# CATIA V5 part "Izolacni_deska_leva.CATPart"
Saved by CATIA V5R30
Part number: Izolacni_deska_leva
Definition: E 1400_396 446_8_90_1
Nomenclature: E 1400_396 446_8_90_1
Source: Unknown
Description: PART--DESC
Bounding box of the stored display mesh (mm): x -223 to 223, y -198 to 198, z -268 to -260
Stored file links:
  E:\Bakalarka\Model\Forma_v7\Izolacni_deska_leva.CATPart
  E:\Bakalarka\Model\Forma_v7\Vyhazovaci_cast.CATProduct
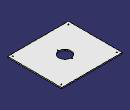
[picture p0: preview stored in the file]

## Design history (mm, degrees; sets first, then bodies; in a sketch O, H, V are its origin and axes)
Body1 "MANIFOLD_SOLID_BREP #3770" (main body)
  Solid1: solid without history
  Body2 "Result of DrillHole"
    Solid2: linked copy from another document
  Assemble1 "DrillHoleLocatingRing_E1362_3.1": tool Body2
  Body3 "Result of DrillHole"
    Solid3: linked copy from another document
  Assemble2 "DrillHoleCapScrew_E1200_1.1": tool Body3
  Body4 "Result of DrillHole"
    Solid4: linked copy from another document
  Assemble3 "DrillHoleCapScrew_E1200_1.2": tool Body4
  Body5 "Result of DrillHole"
    Solid5: linked copy from another document
  Assemble4 "DrillHoleCountersunkScrew_E1220_6.1": tool Body5
  Body6 "Result of DrillHole"
    Solid6: linked copy from another document
  Assemble5 "DrillHoleCountersunkScrew_E1220_6.2": tool Body6
  Body7 "Result of DrillHole"
    Solid7: linked copy from another document
  Assemble6 "DrillHoleCountersunkScrew_E1220_6.3": tool Body7
  Body8 "Result of DrillHole"
    Solid8: linked copy from another document
  Assemble7 "DrillHoleCountersunkScrew_E1220_6.4": tool Body8
  Body9 "Result of DrillHole"
    Solid9: linked copy from another document
  Assemble8 "DrillHoleLocatingRing_E1367_2.1": tool Body9
  Sketch1 on face of Solid1, origin (0, 0, -268), H (1, 0, 0), V (0, -1, 0)
    point P1 (0, 0)
    point P2 (170, 0)
    point P3 (-170, 0)
    distance V P2 = 170
    distance P3 V = 170
    coincidence: P1 O, P2 H, P3 H
  DatumPoint1
  DatumPoint2
  Sketch2 on face of Solid1, origin (0, 0, -268), H (1, 0, 0), V (0, -1, 0)
    point P1 (203.188, -177.0927)
    point P2 (203.188, 179.4827)
    projected point E1 (-203, -178) from vertex of DatumPoint1
    projected point E2 (-203, 178) from vertex of DatumPoint2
